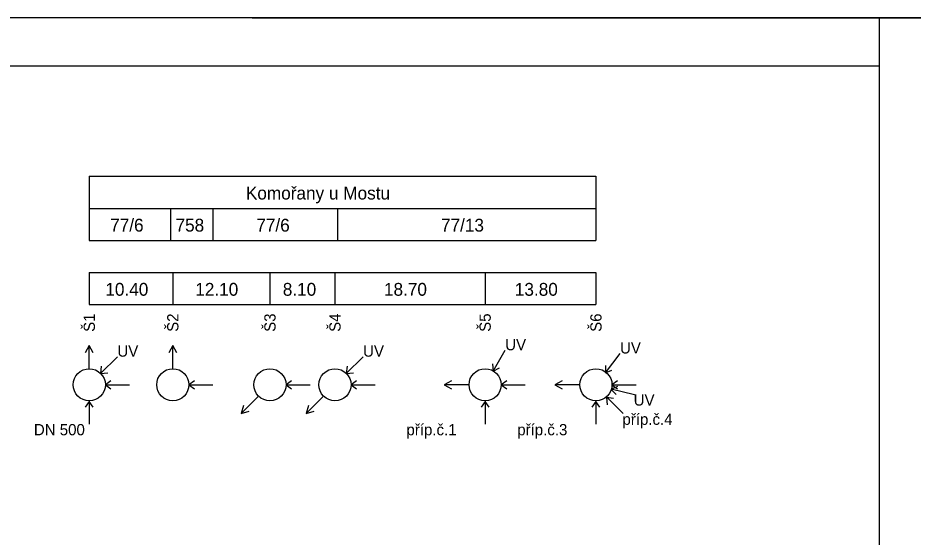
# Model space of a CAD drawing. Extents: x -760612 to 2731, y -975740 to 2995.
# Drawn here: x -442 to 673, y 2348 to 2995 of the extents above; entities that cross this region are included whole.
import ezdxf

# ---------------------------------------------------------------- set-up
doc = ezdxf.new("R2010")
doc.units = 0
for name, color, linetype in [('Border', 7, 'Continuous'), ('Implicitní', 7, 'Continuous'), ('Výřez', 7, 'Continuous')]:
    doc.layers.add(name, color=color, linetype=linetype)

# ---------------------------------------------------------------- blocks, each defined once
blk = doc.blocks.new('A3coversheet_v03_CZ_1_1')
at = {"layer": 'Border'}
blk.add_lwpolyline([(0, 0), (4.2, 0), (4.2, 2.97), (0, 2.97)], close=True, dxfattribs=at)
for points in [[(2.1, 0), (2.1, 2.97), (4.2, 2.97)], [(2.1, 0.07), (0.2, 0.07), (0.2, 2.91), (2.1, 2.91)]]:
    blk.add_lwpolyline(points, dxfattribs=at)

msp = doc.modelspace()

# ---------------------------------------------------------------- linework, layer by layer
at = {"layer": 'Implicitní'}
for p, q in [((-150, 2995), (850, 2995)), ((-353, 2797.5), (-353, 2757.5)), ((-353, 2797.5), (278, 2797.5)), ((278, 2797.5), (278, 2757.5)), ((-353, 2757.5), (-353, 2717.5)), ((-353, 2757.5), (-252, 2757.5)), ((-353, 2757.5), (278, 2757.5)), ((-252, 2757.5), (-252, 2717.5)), ((-252, 2757.5), (-199, 2757.5)), ((-199, 2757.5), (-199, 2717.5)), ((-199, 2757.5), (-44, 2757.5)), ((-44, 2757.5), (-44, 2717.5)), ((-44, 2757.5), (278, 2757.5)), ((278, 2757.5), (278, 2717.5)), ((-353, 2717.5), (-252, 2717.5)), ((-252, 2717.5), (-199, 2717.5)), ((-199, 2717.5), (-44, 2717.5)), ((-44, 2717.5), (278, 2717.5)), ((-353, 2677.5), (-353, 2637.5)), ((-353, 2677.5), (-353, 2677.5)), ((-353, 2677.5), (-353, 2637.5)), ((-353, 2677.5), (-249, 2677.5)), ((-249, 2677.5), (-249, 2637.5)), ((-249, 2677.5), (-128, 2677.5)), ((-128, 2677.5), (-128, 2637.5)), ((-128, 2677.5), (-47, 2677.5)), ((-47, 2677.5), (-47, 2637.5)), ((-47, 2677.5), (140, 2677.5)), ((140, 2677.5), (140, 2637.5)), ((140, 2677.5), (278, 2677.5)), ((278, 2677.5), (278, 2637.5)), ((-353, 2637.5), (-353, 2637.5)), ((-353, 2637.5), (-249, 2637.5)), ((-249, 2637.5), (-128, 2637.5)), ((-128, 2637.5), (-47, 2637.5)), ((-47, 2637.5), (140, 2637.5)), ((140, 2637.5), (278, 2637.5)), ((-353, 2586.5), (-358, 2577.5)), ((-353, 2557.5), (-353, 2586.5)), ((-348, 2577.5), (-353, 2586.5)), ((-249, 2586.5), (-254, 2577.5)), ((-249, 2557.5), (-249, 2586.5)), ((-244, 2577.5), (-249, 2586.5)), ((150, 2554.5), (165, 2580.5)), ((290, 2552.5), (308, 2576.5)), ((-339, 2551.5), (-318, 2572.5)), ((-33, 2551.5), (-12, 2572.5)), ((-338, 2560.5), (-339, 2551.5)), ((-32, 2560.5), (-33, 2551.5)), ((149, 2563.5), (150, 2554.5)), ((150, 2554.5), (158, 2558.5)), ((290, 2561.5), (290, 2552.5)), ((290, 2552.5), (298, 2555.5)), ((-339, 2551.5), (-330, 2552.5)), ((-326, 2542.5), (-333, 2537.5)), ((-222, 2542.5), (-229, 2537.5)), ((-101, 2542.5), (-108, 2537.5)), ((-33, 2551.5), (-24, 2552.5)), ((-20, 2542.5), (-27, 2537.5)), ((98, 2542.5), (89, 2537.5)), ((167, 2542.5), (160, 2537.5)), ((236, 2542.5), (227, 2537.5)), ((305, 2542.5), (298, 2537.5)), ((-333, 2537.5), (-303, 2537.5)), ((-333, 2537.5), (-326, 2532.5)), ((-229, 2537.5), (-199, 2537.5)), ((-229, 2537.5), (-222, 2532.5)), ((-108, 2537.5), (-78, 2537.5)), ((-108, 2537.5), (-101, 2532.5)), ((-27, 2537.5), (3, 2537.5)), ((-27, 2537.5), (-20, 2532.5)), ((89, 2537.5), (98, 2532.5)), ((120, 2537.5), (90, 2537.5)), ((160, 2537.5), (190, 2537.5)), ((160, 2537.5), (167, 2532.5)), ((227, 2537.5), (236, 2532.5)), ((258, 2537.5), (228, 2537.5)), ((305, 2535.5), (297, 2531.5)), ((297, 2532.5), (326, 2525.5)), ((297, 2531.5), (303, 2525.5)), ((298, 2537.5), (328, 2537.5)), ((298, 2537.5), (305, 2532.5)), ((-143, 2522.5), (-163, 2502.5)), ((-62, 2522.5), (-82, 2502.5)), ((291, 2522.5), (312, 2501.5)), ((300, 2520.5), (291, 2521.5)), ((291, 2521.5), (292, 2512.5)), ((-353, 2516.5), (-358, 2509.5)), ((-353, 2517.5), (-353, 2488.5)), ((-348, 2509.5), (-353, 2516.5)), ((-161, 2511.5), (-164, 2501.5)), ((-80, 2511.5), (-83, 2501.5)), ((140, 2516.5), (135, 2509.5)), ((140, 2517.5), (140, 2488.5)), ((145, 2509.5), (140, 2516.5)), ((278, 2516.5), (273, 2509.5)), ((278, 2517.5), (278, 2488.5)), ((283, 2509.5), (278, 2516.5)), ((-164, 2501.5), (-154, 2504.5)), ((-83, 2501.5), (-73, 2504.5))]:
    msp.add_line(p, q, dxfattribs=at)
for centre in [(-353, 2537.5), (-249, 2537.5), (-128, 2537.5), (-47, 2537.5), (140, 2537.5), (278, 2537.5)]:
    msp.add_circle(centre, 20, dxfattribs=at)
at = {"layer": 'Výřez'}
msp.add_lwpolyline([(-1469, 25), (2731, 25), (2731, 2995), (-1469, 2995)], close=True, dxfattribs=at)

# ---------------------------------------------------------------- block references
at = {"layer": 'Border', "xscale": 1000.0000004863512, "yscale": 1000.0000004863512, "rotation": 4.518606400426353e-10}
msp.add_blockref('A3coversheet_v03_CZ_1_1', (-1469, 25), dxfattribs=at)

# ---------------------------------------------------------------- texts
at = {"layer": 'Implicitní'}
for s, height, p in [('Komořany u Mostu', 16, (-158, 2768.5)), ('77/6', 16, (-327, 2728.5)), ('758', 16, (-245.6, 2728.5)), ('77/6', 16, (-145, 2728.5)), ('77/13', 16, (85, 2728.5)), ('10.40', 16, (-333, 2648.5)), ('12.10', 16, (-221, 2648.5)), ('8.10', 16, (-112, 2648.5)), ('18.70', 16, (14, 2648.5)), ('13.80', 16, (177, 2648.5)), ('UV', 14, (165, 2580.5)), ('UV', 14, (308, 2576.5)), ('UV', 14, (-318, 2572.5)), ('UV', 14, (-12, 2572.5)), ('UV', 14, (325, 2511.5)), ('příp.č.4', 14, (311, 2487.5)), ('DN 500', 14, (-422, 2474.5)), ('příp.č.1', 14, (42, 2474.5)), ('příp.č.3', 14, (180, 2474.5))]:
    msp.add_text(s, height=height, dxfattribs=at).set_placement(p)
for s, p in [('Š1', (-346, 2603.5)), ('Š2', (-242, 2603.5)), ('Š3', (-121, 2603.5)), ('Š4', (-40, 2603.5)), ('Š5', (147, 2603.5)), ('Š6', (285, 2603.5))]:
    msp.add_text(s, height=14, rotation=90, dxfattribs=at).set_placement(p)

doc.saveas('drawing.dxf')
